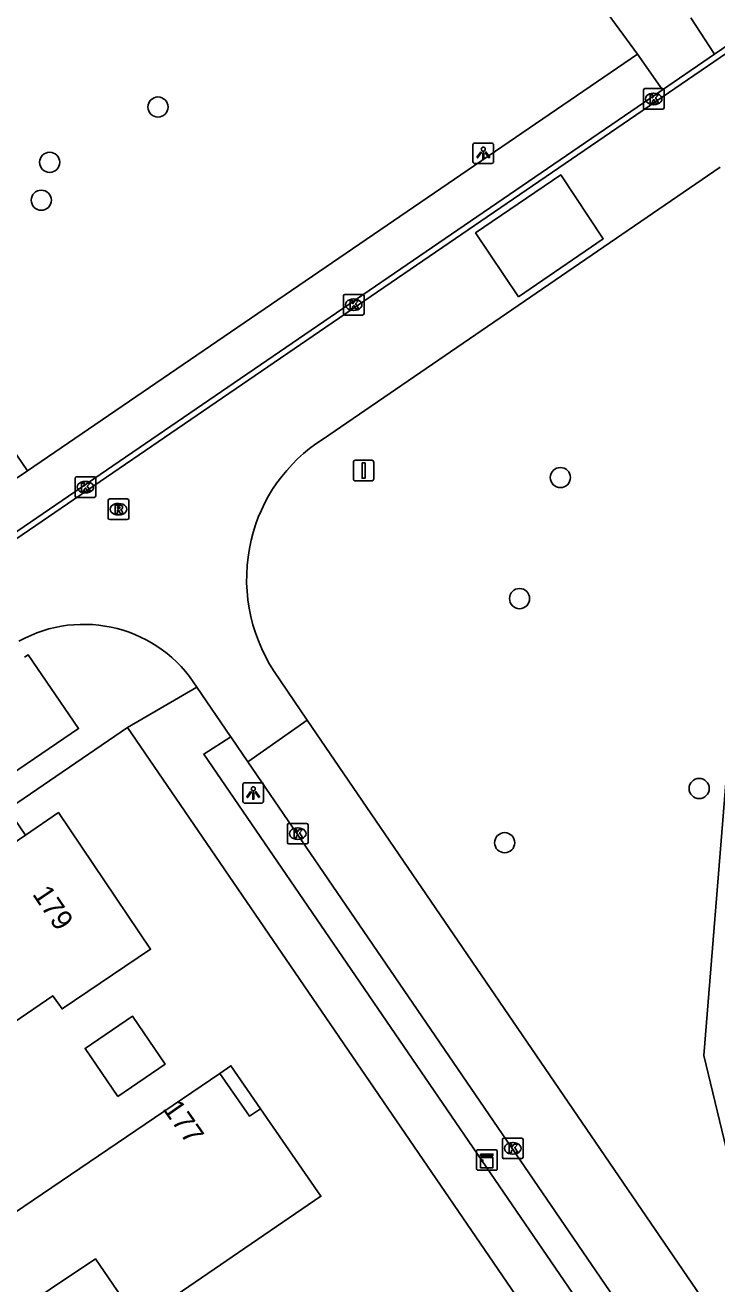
# Model space of a CAD drawing. Extents: x 155275 to 156263, y 382654 to 383635.
# Drawn here: x 155549.6 to 155583.1, y 383335.2 to 383396.3 of the extents above; entities that cross this region are included whole.
import ezdxf

# ---------------------------------------------------------------- set-up
doc = ezdxf.new("R2010")
doc.units = 0
for name, color, linetype in [('IMGEO_Boom', 7, 'Continuous'), ('IMGEO_Fietspad_gesloten', 7, 'Continuous'), ('IMGEO_Gemengd_bos', 7, 'Continuous'), ('IMGEO_Haag', 7, 'Continuous'), ('IMGEO_Kast', 7, 'Continuous'), ('IMGEO_Kolk', 7, 'Continuous'), ('IMGEO_Lichtpunt', 7, 'Continuous'), ('IMGEO_Pand', 7, 'Continuous'), ('IMGEO_Pand_nummerreeks', 7, 'Continuous'), ('IMGEO_Pand_overbouw', 7, 'Continuous'), ('IMGEO_Rijbaan_lokaal_gesloten', 7, 'Continuous'), ('IMGEO_Rijbaan_lokaal_open', 7, 'Continuous'), ('IMGEO_Rioolput', 7, 'Continuous'), ('IMGEO_Verkeersbordpaal', 7, 'Continuous'), ('IMGEO_Voetpad_open', 7, 'Continuous')]:
    doc.layers.add(name, color=color, linetype=linetype)

msp = doc.modelspace()

# ---------------------------------------------------------------- linework, layer by layer
at = {"layer": 'IMGEO_Boom'}
for centre in [(155556.012, 383392.364), (155550.752, 383389.677), (155550.346, 383387.835), (155575.549, 383374.363), (155573.568, 383368.482), (155582.289, 383359.258), (155572.844, 383356.623)]:
    msp.add_circle(centre, 0.489, dxfattribs=at)
at = {"layer": 'IMGEO_Fietspad_gesloten'}
for points in [[(155575.918, 383399.274), (155576.851, 383398.278), (155579.299, 383394.927)], [(155583.028, 383394.932), (155581.886, 383396.704)], [(155579.299, 383394.927), (155580.501, 383393.203)]]:
    msp.add_lwpolyline(points, dxfattribs=at)
at = {"layer": 'IMGEO_Gemengd_bos'}
msp.add_lwpolyline([(155592.715, 383342.202), (155584.702, 383337.218), (155582.518, 383346.285), (155584.689, 383373.163), (155587.497, 383375.972)], dxfattribs=at)
at = {"layer": 'IMGEO_Haag'}
msp.add_lwpolyline([(155515.668, 383424.609), (155549.681, 383374.692)], dxfattribs=at)
at = {"layer": 'IMGEO_Kast'}
for p, q in [((155571.555, 383341.708), (155572.396, 383341.708)), ((155572.396, 383341.708), (155571.555, 383341.708)), ((155571.48, 383340.783), (155571.48, 383341.624)), ((155571.48, 383341.624), (155571.48, 383340.783)), ((155572.48, 383341.633), (155572.48, 383340.792)), ((155572.48, 383340.792), (155572.48, 383341.633)), ((155572.405, 383340.708), (155571.564, 383340.708)), ((155571.564, 383340.708), (155572.405, 383340.708))]:
    msp.add_line(p, q, dxfattribs=at)
for points in [[(155571.675, 383341.498), (155572.275, 383341.498), (155572.275, 383341.413), (155571.675, 383341.413), (155571.675, 383341.498)], [(155571.675, 383341.323), (155572.275, 383341.323), (155572.275, 383340.834), (155571.675, 383340.834), (155571.675, 383341.323)]]:
    msp.add_lwpolyline(points, dxfattribs=at)
msp.add_circle((155571.759, 383341.172), 0.0377, dxfattribs=at)
for centre, start, end in [((155571.558, 383341.63), 92.4484, 184.28452), ((155571.558, 383341.63), 92.4484, 184.28452), ((155572.402, 383341.63), 2.4484, 94.28452), ((155572.402, 383341.63), 2.4484, 94.28452), ((155571.558, 383340.786), 182.4484, 274.28452), ((155571.558, 383340.786), 182.4484, 274.28452), ((155572.402, 383340.786), 272.4484, 4.28452), ((155572.402, 383340.786), 272.4484, 4.28452)]:
    msp.add_arc(centre, 0.0779, start, end, dxfattribs=at)
at = {"layer": 'IMGEO_Kolk'}
for p, q in [((155579.581, 383392.332), (155579.581, 383393.184)), ((155579.656, 383393.258), (155580.508, 383393.258)), ((155580.582, 383393.184), (155580.582, 383392.332)), ((155580.092, 383392.478), (155580.067, 383392.478)), ((155580.069, 383393.038), (155580.094, 383393.038)), ((155580.508, 383392.258), (155579.656, 383392.258)), ((155565.014, 383382.333), (155565.014, 383383.185)), ((155565.089, 383383.259), (155565.941, 383383.259)), ((155565.502, 383383.039), (155565.527, 383383.039)), ((155566.015, 383383.185), (155566.015, 383382.333)), ((155565.941, 383382.259), (155565.089, 383382.259)), ((155565.525, 383382.479), (155565.5, 383382.479)), ((155551.985, 383373.472), (155551.985, 383374.324)), ((155552.06, 383374.398), (155552.912, 383374.398)), ((155552.473, 383374.178), (155552.498, 383374.178)), ((155552.986, 383374.324), (155552.986, 383373.472)), ((155552.496, 383373.618), (155552.471, 383373.618)), ((155552.912, 383373.398), (155552.06, 383373.398)), ((155562.297, 383356.636), (155562.297, 383357.488)), ((155562.372, 383357.562), (155563.224, 383357.562)), ((155562.785, 383357.342), (155562.81, 383357.342)), ((155563.298, 383357.488), (155563.298, 383356.636)), ((155563.224, 383356.562), (155562.372, 383356.562)), ((155562.808, 383356.782), (155562.783, 383356.782)), ((155572.738, 383341.348), (155572.738, 383342.2)), ((155572.813, 383342.274), (155573.665, 383342.274)), ((155573.226, 383342.054), (155573.251, 383342.054)), ((155573.739, 383342.2), (155573.739, 383341.348)), ((155573.665, 383341.274), (155572.813, 383341.274)), ((155573.249, 383341.494), (155573.224, 383341.494))]:
    msp.add_line(p, q, dxfattribs=at)
for points in [[(155579.581, 383392.332), (155579.581, 383393.184)], [(155579.656, 383393.258), (155580.508, 383393.258)], [(155580.582, 383393.184), (155580.582, 383392.332)], [(155579.902, 383392.958), (155580.025, 383392.958), (155580.025, 383392.807), (155580.155, 383392.958), (155580.319, 383392.958), (155580.173, 383392.807), (155580.326, 383392.558), (155580.174, 383392.558), (155580.089, 383392.722), (155580.025, 383392.655), (155580.025, 383392.558), (155579.902, 383392.558), (155579.902, 383392.958)], [(155580.508, 383392.258), (155579.656, 383392.258)], [(155565.014, 383382.333), (155565.014, 383383.185)], [(155565.089, 383383.259), (155565.941, 383383.259)], [(155565.335, 383382.959), (155565.458, 383382.959), (155565.458, 383382.808), (155565.588, 383382.959), (155565.752, 383382.959), (155565.606, 383382.808), (155565.759, 383382.559), (155565.607, 383382.559), (155565.522, 383382.723), (155565.458, 383382.656), (155565.458, 383382.559), (155565.335, 383382.559), (155565.335, 383382.959)], [(155566.015, 383383.185), (155566.015, 383382.333)], [(155565.941, 383382.259), (155565.089, 383382.259)], [(155551.985, 383373.472), (155551.985, 383374.324)], [(155552.06, 383374.398), (155552.912, 383374.398)], [(155552.986, 383374.324), (155552.986, 383373.472)], [(155552.306, 383374.098), (155552.429, 383374.098), (155552.429, 383373.947), (155552.559, 383374.098), (155552.723, 383374.098), (155552.577, 383373.947), (155552.73, 383373.698), (155552.578, 383373.698), (155552.493, 383373.862), (155552.429, 383373.795), (155552.429, 383373.698), (155552.306, 383373.698), (155552.306, 383374.098)], [(155552.912, 383373.398), (155552.06, 383373.398)], [(155562.297, 383356.636), (155562.297, 383357.488)], [(155562.372, 383357.562), (155563.224, 383357.562)], [(155562.618, 383357.262), (155562.741, 383357.262), (155562.741, 383357.111), (155562.871, 383357.262), (155563.035, 383357.262), (155562.889, 383357.111), (155563.042, 383356.862), (155562.89, 383356.862), (155562.805, 383357.026), (155562.741, 383356.959), (155562.741, 383356.862), (155562.618, 383356.862), (155562.618, 383357.262)], [(155563.298, 383357.488), (155563.298, 383356.636)], [(155563.224, 383356.562), (155562.372, 383356.562)], [(155572.738, 383341.348), (155572.738, 383342.2)], [(155572.813, 383342.274), (155573.665, 383342.274)], [(155573.059, 383341.974), (155573.182, 383341.974), (155573.182, 383341.823), (155573.312, 383341.974), (155573.476, 383341.974), (155573.33, 383341.823), (155573.483, 383341.574), (155573.331, 383341.574), (155573.246, 383341.738), (155573.182, 383341.671), (155573.182, 383341.574), (155573.059, 383341.574), (155573.059, 383341.974)], [(155573.739, 383342.2), (155573.739, 383341.348)], [(155573.665, 383341.274), (155572.813, 383341.274)]]:
    msp.add_lwpolyline(points, dxfattribs=at)
for centre, start, end in [((155579.658, 383393.182), 91.55205, 178.44795), ((155579.658, 383393.182), 91.55205, 178.44795), ((155580.506, 383393.182), 1.55205, 88.44795), ((155580.506, 383393.182), 1.55205, 88.44795), ((155579.658, 383392.334), 181.55205, 268.44795), ((155579.658, 383392.334), 181.55205, 268.44795), ((155580.506, 383392.334), 271.55205, 358.44795), ((155580.506, 383392.334), 271.55205, 358.44795), ((155565.091, 383383.183), 91.55205, 178.44795), ((155565.091, 383383.183), 91.55205, 178.44795), ((155565.939, 383383.183), 1.55205, 88.44795), ((155565.939, 383383.183), 1.55205, 88.44795), ((155565.091, 383382.335), 181.55205, 268.44795), ((155565.091, 383382.335), 181.55205, 268.44795), ((155565.939, 383382.335), 271.55205, 358.44795), ((155565.939, 383382.335), 271.55205, 358.44795), ((155552.062, 383374.322), 91.55205, 178.44795), ((155552.062, 383374.322), 91.55205, 178.44795), ((155552.91, 383374.322), 1.55205, 88.44795), ((155552.91, 383374.322), 1.55205, 88.44795), ((155552.062, 383373.474), 181.55205, 268.44795), ((155552.062, 383373.474), 181.55205, 268.44795), ((155552.91, 383373.474), 271.55205, 358.44795), ((155552.91, 383373.474), 271.55205, 358.44795), ((155562.374, 383357.486), 91.55205, 178.44795), ((155562.374, 383357.486), 91.55205, 178.44795), ((155563.222, 383357.486), 1.55205, 88.44795), ((155563.222, 383357.486), 1.55205, 88.44795), ((155562.374, 383356.638), 181.55205, 268.44795), ((155562.374, 383356.638), 181.55205, 268.44795), ((155563.222, 383356.638), 271.55205, 358.44795), ((155563.222, 383356.638), 271.55205, 358.44795), ((155572.815, 383342.198), 91.55205, 178.44795), ((155572.815, 383342.198), 91.55205, 178.44795), ((155573.663, 383342.198), 1.55205, 88.44795), ((155573.663, 383342.198), 1.55205, 88.44795), ((155572.815, 383341.35), 181.55205, 268.44795), ((155572.815, 383341.35), 181.55205, 268.44795), ((155573.663, 383341.35), 271.55205, 358.44795), ((155573.663, 383341.35), 271.55205, 358.44795)]:
    msp.add_arc(centre, 0.0765, start, end, dxfattribs=at)
for centre, major_axis, ratio, start_param, end_param in [((155580.068, 383392.758), (-0.387, 0.002), 0.722429, 4.712389, 7.853982), ((155580.093, 383392.758), (-0.39, 0.002), 0.717154, 1.570796, 4.712389), ((155565.501, 383382.759), (-0.387, 0.002), 0.722429, 4.712389, 7.853982), ((155565.526, 383382.759), (-0.39, 0.002), 0.717154, 1.570796, 4.712389), ((155552.472, 383373.898), (-0.387, 0.002), 0.722429, 4.712389, 7.853982), ((155552.497, 383373.898), (-0.39, 0.002), 0.717154, 1.570796, 4.712389), ((155562.784, 383357.062), (-0.387, 0.002), 0.722429, 4.712389, 7.853982), ((155562.809, 383357.062), (-0.39, 0.002), 0.717154, 1.570796, 4.712389), ((155573.225, 383341.774), (-0.387, 0.002), 0.722429, 4.712389, 7.853982), ((155573.25, 383341.774), (-0.39, 0.002), 0.717154, 1.570796, 4.712389)]:
    msp.add_ellipse(centre, major_axis=major_axis, ratio=ratio, start_param=start_param, end_param=end_param, dxfattribs=at)
at = {"layer": 'IMGEO_Lichtpunt'}
for p, q in [((155572.208, 383390.614), (155571.4, 383390.614)), ((155572.208, 383390.614), (155571.4, 383390.614)), ((155571.306, 383390.519), (155571.306, 383389.712)), ((155571.306, 383390.519), (155571.306, 383389.712)), ((155572.302, 383389.712), (155572.302, 383390.519)), ((155572.302, 383389.712), (155572.302, 383390.519)), ((155571.4, 383389.618), (155572.208, 383389.618)), ((155571.4, 383389.618), (155572.208, 383389.618)), ((155560.137, 383359.444), (155560.137, 383358.637)), ((155560.137, 383359.444), (155560.137, 383358.637)), ((155561.039, 383359.539), (155560.231, 383359.539)), ((155561.039, 383359.539), (155560.231, 383359.539)), ((155561.133, 383358.637), (155561.133, 383359.444)), ((155561.133, 383358.637), (155561.133, 383359.444)), ((155560.231, 383358.543), (155561.039, 383358.543)), ((155560.231, 383358.543), (155561.039, 383358.543))]:
    msp.add_line(p, q, dxfattribs=at)
for points in [[(155571.68, 383390.183), (155571.719, 383390.155), (155571.531, 383389.893), (155571.493, 383389.92), (155571.68, 383390.183)], [(155571.782, 383390.135), (155571.829, 383390.135), (155571.829, 383389.813), (155571.782, 383389.813), (155571.782, 383390.135)], [(155571.892, 383390.155), (155571.93, 383390.182), (155572.117, 383389.92), (155572.078, 383389.892), (155571.892, 383390.155)], [(155560.511, 383359.108), (155560.55, 383359.08), (155560.362, 383358.818), (155560.324, 383358.845), (155560.511, 383359.108)], [(155560.613, 383359.06), (155560.66, 383359.06), (155560.66, 383358.738), (155560.613, 383358.738), (155560.613, 383359.06)], [(155560.723, 383359.08), (155560.761, 383359.107), (155560.948, 383358.845), (155560.909, 383358.817), (155560.723, 383359.08)]]:
    msp.add_lwpolyline(points, dxfattribs=at)
for centre in [(155571.805, 383390.317), (155560.636, 383359.242)]:
    msp.add_circle(centre, 0.0994, dxfattribs=at)
for centre, start, end in [((155571.4, 383390.519), 90, 180), ((155571.4, 383390.519), 90, 180), ((155572.208, 383390.519), 0, 90), ((155572.208, 383390.519), 0, 90), ((155571.4, 383389.712), 180, 270), ((155571.4, 383389.712), 180, 270), ((155572.208, 383389.712), 270, 0), ((155572.208, 383389.712), 270, 360), ((155560.231, 383359.444), 90, 180), ((155560.231, 383359.444), 90, 180), ((155561.039, 383359.444), 0, 90), ((155561.039, 383359.444), 0, 90), ((155560.231, 383358.637), 180, 270), ((155560.231, 383358.637), 180, 270), ((155561.039, 383358.637), 270, 0), ((155561.039, 383358.637), 270, 360)]:
    msp.add_arc(centre, 0.0946, start, end, dxfattribs=at)
at = {"layer": 'IMGEO_Pand'}
for points in [[(155545.875, 383345.753), (155544.143, 383348.308), (155540.963, 383346.186), (155539.315, 383348.678), (155536.308, 383346.626), (155534.904, 383348.672), (155544.09, 383354.95), (155544.874, 383353.792), (155549.582, 383356.997), (155551.174, 383358.087), (155555.656, 383351.45), (155551.358, 383348.545), (155550.905, 383349.19), (155545.875, 383345.753)], [(155554.063, 383344.295), (155552.47, 383346.629), (155554.771, 383348.2), (155556.364, 383345.865), (155554.063, 383344.295)], [(155555.044, 383333.379), (155552.972, 383336.407), (155548.571, 383333.467), (155546.313, 383336.792), (155559.011, 383345.413), (155560.461, 383343.338), (155560.986, 383343.698), (155563.925, 383339.448), (155555.044, 383333.379)]]:
    msp.add_lwpolyline(points, dxfattribs=at)
at = {"layer": 'IMGEO_Pand_overbouw'}
for points in [[(155549.582, 383356.997), (155548.787, 383358.161), (155544.09, 383354.95), (155544.874, 383353.792)], [(155560.986, 383343.698), (155559.552, 383345.787), (155559.011, 383345.413), (155560.461, 383343.338)]]:
    msp.add_lwpolyline(points, close=True, dxfattribs=at)
at = {"layer": 'IMGEO_Rijbaan_lokaal_gesloten'}
for points in [[(155560.376, 383360.557), (155563.253, 383362.574)], [(155563.253, 383362.574), (155623.958, 383273.666)], [(155621.067, 383271.724), (155560.376, 383360.557)]]:
    msp.add_lwpolyline(points, dxfattribs=at)
at = {"layer": 'IMGEO_Rijbaan_lokaal_open'}
for points in [[(155600.872, 383406.808), (155545.973, 383369.225)], [(155583.028, 383394.932), (155600.732, 383407.049)], [(155580.501, 383393.203), (155583.028, 383394.932)], [(155517.529, 383350.104), (155580.501, 383393.203)], [(155564.006, 383376.217), (155583.312, 383389.439)], [(155573.512, 383383.144), (155571.431, 383386.247), (155575.566, 383389.064), (155577.634, 383385.963), (155573.512, 383383.144)], [(155563.253, 383362.574), (155561.654, 383364.944)], [(155557.903, 383364.172), (155559.538, 383361.779), (155559.546, 383361.767)], [(155559.546, 383361.767), (155559.574, 383361.726), (155560.376, 383360.557)]]:
    msp.add_lwpolyline(points, dxfattribs=at)
for centre, radius, start, end in [((155568.245, 383369.535), 7.913, 122.3933, 166.93555), ((155568.482, 383369.427), 8.168, 166.5718, 213.2894), ((155552.414, 383360.778), 6.453, 31.73023, 119.27907)]:
    msp.add_arc(centre, radius, start, end, dxfattribs=at)
at = {"layer": 'IMGEO_Rioolput'}
for p, q in [((155553.593, 383372.398), (155553.593, 383373.25)), ((155553.668, 383373.324), (155554.52, 383373.324)), ((155554.081, 383373.104), (155554.106, 383373.104)), ((155554.594, 383373.25), (155554.594, 383372.398)), ((155554.52, 383372.324), (155553.668, 383372.324)), ((155554.104, 383372.544), (155554.079, 383372.544))]:
    msp.add_line(p, q, dxfattribs=at)
for points in [[(155553.593, 383372.398), (155553.593, 383373.25)], [(155553.668, 383373.324), (155554.52, 383373.324)], [(155554.182, 383373.022), (155553.93, 383373.024), (155553.93, 383372.624)], [(155554.108, 383372.943), (155554.054, 383372.943), (155554.054, 383372.862)], [(155554.594, 383373.25), (155554.594, 383372.398)], [(155554.52, 383372.324), (155553.668, 383372.324)], [(155553.93, 383372.624), (155554.054, 383372.624), (155554.054, 383372.786), (155554.065, 383372.786)], [(155554.054, 383372.862), (155554.106, 383372.862)], [(155554.112, 383372.757), (155554.183, 383372.624), (155554.323, 383372.624), (155554.258, 383372.75)]]:
    msp.add_lwpolyline(points, dxfattribs=at)
for centre, radius, start, end in [((155553.67, 383373.248), 0.0765, 91.55205, 178.44795), ((155553.67, 383373.248), 0.0765, 91.55205, 178.44795), ((155554.114, 383372.847), 0.0964, 77.00612, 93.18647), ((155554.128, 383372.904), 0.0378, 276.66336, 79.67722), ((155554.181, 383372.912), 0.109, 350.36119, 89.41601), ((155554.179, 383372.912), 0.112, 277.58423, 350.98172), ((155554.518, 383373.248), 0.0765, 1.55205, 88.44795), ((155554.518, 383373.248), 0.0765, 1.55205, 88.44795), ((155553.67, 383372.4), 0.0765, 181.55205, 268.44795), ((155553.67, 383372.4), 0.0765, 181.55205, 268.44795), ((155554.064, 383372.733), 0.0533, 26.02933, 88.69889), ((155554.09, 383373.051), 0.19, 274.7715, 282.96867), ((155554.163, 383372.697), 0.108, 29.51342, 73.79051), ((155554.518, 383372.4), 0.0765, 271.55205, 358.44795), ((155554.518, 383372.4), 0.0765, 271.55205, 358.44795)]:
    msp.add_arc(centre, radius, start, end, dxfattribs=at)
for centre, major_axis, ratio, start_param, end_param in [((155554.08, 383372.824), (-0.387, 0.002), 0.722429, 4.712389, 7.853982), ((155554.105, 383372.824), (-0.39, 0.002), 0.717154, 1.570796, 4.712389)]:
    msp.add_ellipse(centre, major_axis=major_axis, ratio=ratio, start_param=start_param, end_param=end_param, dxfattribs=at)
at = {"layer": 'IMGEO_Verkeersbordpaal'}
for p, q in [((155565.498, 383374.302), (155565.498, 383375.102)), ((155565.498, 383375.102), (155565.498, 383374.302)), ((155565.598, 383375.202), (155566.388, 383375.202)), ((155566.388, 383375.202), (155565.598, 383375.202)), ((155566.488, 383375.102), (155566.488, 383374.302)), ((155566.488, 383374.302), (155566.488, 383375.102)), ((155566.388, 383374.202), (155565.598, 383374.202)), ((155565.598, 383374.202), (155566.388, 383374.202))]:
    msp.add_line(p, q, dxfattribs=at)
msp.add_lwpolyline([(155565.918, 383375.077), (155566.068, 383375.077), (155566.068, 383374.327), (155565.918, 383374.327), (155565.918, 383375.077)], dxfattribs=at)
for centre, start, end in [((155565.598, 383375.102), 90, 180), ((155565.598, 383375.102), 90, 180), ((155566.388, 383375.102), 0, 90), ((155566.388, 383375.102), 360, 90), ((155565.598, 383374.302), 180, 270), ((155565.598, 383374.302), 180, 270), ((155566.388, 383374.302), 270, 0), ((155566.388, 383374.302), 270, 0)]:
    msp.add_arc(centre, 0.1, start, end, dxfattribs=at)
at = {"layer": 'IMGEO_Voetpad_open'}
for points in [[(155549.681, 383374.692), (155579.299, 383394.927)], [(155549.13, 383374.315), (155549.681, 383374.692)], [(155549.531, 383365.636), (155549.701, 383365.753), (155552.16, 383362.169), (155542.073, 383355.304)], [(155554.524, 383362.222), (155557.903, 383364.172)], [(155521.756, 383339.814), (155554.524, 383362.222)], [(155618.427, 383268.752), (155618.124, 383269.195), (155554.524, 383362.222)], [(155622.743, 383266.603), (155622.545, 383266.887), (155558.233, 383360.928), (155559.546, 383361.767)]]:
    msp.add_lwpolyline(points, dxfattribs=at)

# ---------------------------------------------------------------- texts
at = {"layer": 'IMGEO_Pand_nummerreeks'}
for s, rotation, p in [('179', 303.99584, (155549.886, 383354.122)), ('177', 304.93975, (155556.209, 383343.698))]:
    msp.add_text(s, height=1, rotation=rotation, dxfattribs=at).set_placement(p)

doc.saveas('drawing.dxf')
